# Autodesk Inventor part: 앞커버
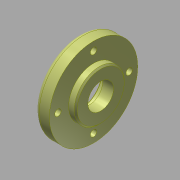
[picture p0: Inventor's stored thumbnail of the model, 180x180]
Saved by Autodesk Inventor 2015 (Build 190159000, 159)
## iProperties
Created: 2015-12
Part Number: 앞커버
Document SubType Name: Modeling
Designer: mdu
Density: 2.71 g/cm^3
Material: 알루미늄 6061
Mass: 70.9323 g
Surface Area: 93.9278 cm^2
Volume: 26.1743 cm^3
Appearance: 알루미늄 - 평지
Author: mdu
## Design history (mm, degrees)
sketch "스케치1"
  geometry: L1 (-7.5, 0)-(7.5, 0); L2 (-7.5, 0)-(-7.5, 31); L3 (-7.5, 31)-(2.5, 31); L4 (2.5, 31)-(2.5, 17.5); L5 (2.5, 17.5)-(7.5, 17.5); L6 (7.5, 17.5)-(7.5, 0); 2 further points
  constraints: 12 end point, 3 perpendicular, 1 coincident, 1 horizontal, 1 midpoint, 1 parallel
  dimensions: "d0" = 15 distance of L1.start L1.end; "d1" = 62 diameter of L3 L1; "d2" = 35 diameter of L5 L1; "d5" = 10 distance of L2.end L3.end
revolve "회전1" sketch "스케치1" stored, may be unused: angle "d6" = 90 deg
sketch "스케치2" dims "d42" = 50
  geometry: 3 further points
  constraints: 2 vertical alignment, 1 coincident, 2 other
hole "구멍1" sketch "스케치2" at (0, 25) diameter "d8" = 4.5; stored, may be unused: countersink angle "d12" = 90 deg, drill point angle "d14" = 118 deg; dims "d9" = 6, "d10" = 8, "d11" = 4.4, "d13" = 8
hole "구멍2" diameter "d20" = 18; stored, may be unused: countersink angle "d24" = 90 deg, drill point angle "d26" = 0 deg; dims "d18" = 10, "d19" = 10, "d21" = 6, "d22" = 8, "d23" = 4.4, "d25" = 8
hole "구멍3" diameter "d34" = 30; stored, may be unused: countersink angle "d38" = 90 deg, drill point angle "d40" = 0 deg; dims "d32" = 10, "d33" = 10, "d35" = 6, "d36" = 4, "d37" = 2, "d39" = 7.3
fillet "모깎기1" dims "d27" = 3, "d41" = 0.3
chamfer "모따기1" distance "d29" = 1; stored, may be unused: second distance "d30" = 2, angle "d31" = 45 deg
node "솔리드1"
pattern_circular "원형 패턴1" dims angle "d16" = 360 deg
